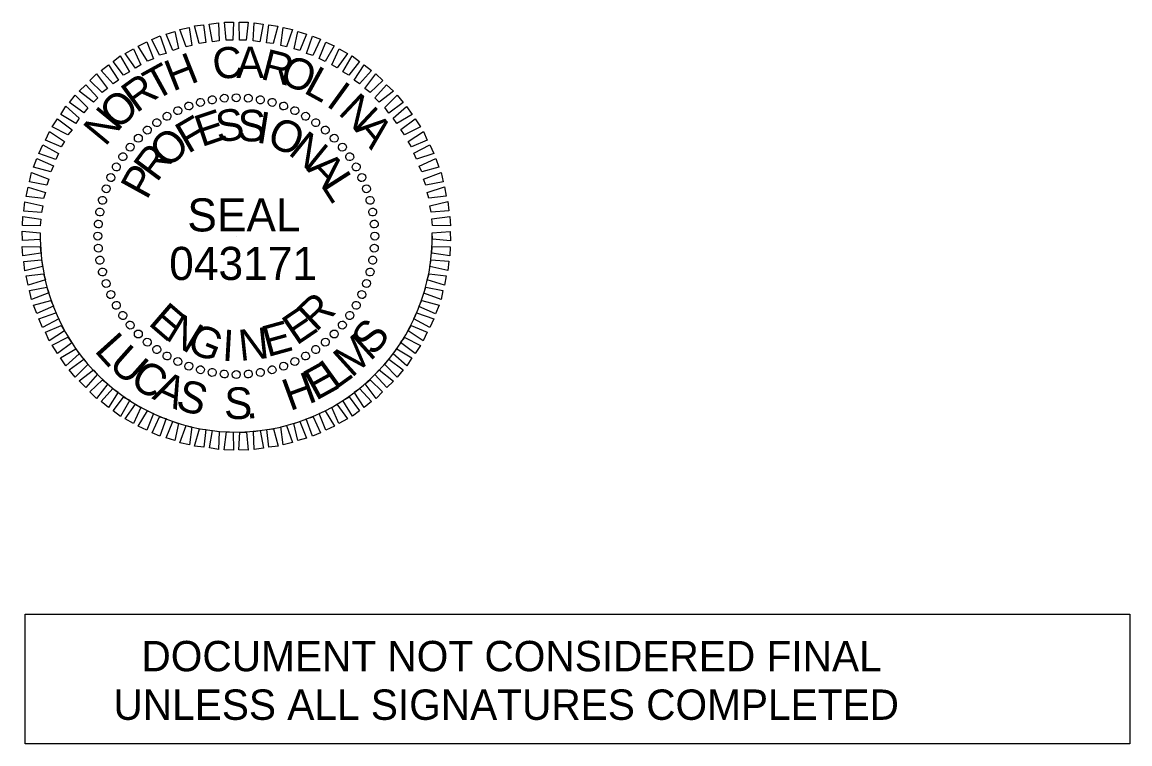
# Model space of a CAD drawing. Extents: x 573078 to 573156.2, y -55225.7 to -55195.8.
# Drawn here: x 573113.18 to 573117.192, y -55203.396 to -55200.78 of the extents above; entities that cross this region are included whole.
import ezdxf

# ---------------------------------------------------------------- set-up
doc = ezdxf.new("R2010")
doc.units = 0
doc.layers.add('Prop Dimension', color=7, linetype='Continuous')
doc.layers.add('Sheet Sticker Exception Certification CELL', color=7, linetype='Continuous')

msp = doc.modelspace()

# ---------------------------------------------------------------- linework, layer by layer
at = {"layer": 'Prop Dimension'}
for p, q in [((573113.7833, -55201.0835), (573113.7833, -55201.0835)), ((573113.8251, -55201.0708), (573113.8251, -55201.0708)), ((573113.869, -55201.062), (573113.869, -55201.062)), ((573113.9118, -55201.0553), (573113.9118, -55201.0553)), ((573113.9558, -55201.0535), (573113.9558, -55201.0535)), ((573113.9999, -55201.0557), (573113.9999, -55201.0557)), ((573114.043, -55201.062), (573114.043, -55201.062)), ((573114.0851, -55201.0703), (573114.0851, -55201.0703)), ((573114.1274, -55201.0835), (573114.1274, -55201.0835)), ((573113.705, -55201.1209), (573113.705, -55201.1209)), ((573113.7436, -55201.1002), (573113.7436, -55201.1002)), ((573114.1677, -55201.1008), (573114.1677, -55201.1008)), ((573114.207, -55201.1201), (573114.207, -55201.1201)), ((573113.6674, -55201.1446), (573113.6674, -55201.1446)), ((573114.2435, -55201.1445), (573114.2435, -55201.1445)), ((573113.6003, -55201.2007), (573113.6003, -55201.2007)), ((573113.6328, -55201.1702), (573113.6328, -55201.1702)), ((573114.2789, -55201.1709), (573114.2789, -55201.1709)), ((573114.3104, -55201.2003), (573114.3104, -55201.2003)), ((573113.5709, -55201.2323), (573113.5709, -55201.2323)), ((573114.341, -55201.2328), (573114.341, -55201.2328)), ((573113.5445, -55201.2677), (573113.5445, -55201.2677)), ((573114.3666, -55201.2674), (573114.3666, -55201.2674)), ((573113.5201, -55201.3041), (573113.5201, -55201.3041)), ((573114.3903, -55201.305), (573114.3903, -55201.305)), ((573113.5008, -55201.3435), (573113.5008, -55201.3435)), ((573114.411, -55201.3436), (573114.411, -55201.3436)), ((573113.4835, -55201.3838), (573113.4835, -55201.3838)), ((573114.4276, -55201.3833), (573114.4276, -55201.3833)), ((573113.4702, -55201.426), (573113.4702, -55201.426)), ((573114.4404, -55201.4251), (573114.4404, -55201.4251)), ((573113.462, -55201.4682), (573113.462, -55201.4682)), ((573114.4491, -55201.469), (573114.4491, -55201.469)), ((573113.4557, -55201.5113), (573113.4557, -55201.5113)), ((573114.4559, -55201.5118), (573114.4559, -55201.5118)), ((573113.4535, -55201.5554), (573113.4535, -55201.5554)), ((573113.9556, -55201.5556), (573113.9556, -55201.5556)), ((573114.4577, -55201.5558), (573114.4577, -55201.5558)), ((573113.4553, -55201.5993), (573113.4553, -55201.5993)), ((573114.4554, -55201.5999), (573114.4554, -55201.5999)), ((573113.462, -55201.6422), (573113.462, -55201.6422)), ((573114.4492, -55201.643), (573114.4492, -55201.643)), ((573113.4708, -55201.6861), (573113.4708, -55201.6861)), ((573114.4409, -55201.6851), (573114.4409, -55201.6851)), ((573114.4277, -55201.7274), (573114.4277, -55201.7274)), ((573113.4835, -55201.7279), (573113.4835, -55201.7279)), ((573113.5002, -55201.7676), (573113.5002, -55201.7676)), ((573114.4104, -55201.7677), (573114.4104, -55201.7677)), ((573113.5209, -55201.8062), (573113.5209, -55201.8062)), ((573114.391, -55201.807), (573114.391, -55201.807)), ((573113.5446, -55201.8438), (573113.5446, -55201.8438)), ((573114.3667, -55201.8435), (573114.3667, -55201.8435)), ((573113.5702, -55201.8784), (573113.5702, -55201.8784)), ((573114.3403, -55201.8789), (573114.3403, -55201.8789)), ((573113.6007, -55201.9108), (573113.6007, -55201.9108)), ((573114.3108, -55201.9104), (573114.3108, -55201.9104)), ((573113.6322, -55201.9403), (573113.6322, -55201.9403)), ((573113.6677, -55201.9667), (573113.6677, -55201.9667)), ((573114.2438, -55201.9666), (573114.2438, -55201.9666)), ((573114.2784, -55201.941), (573114.2784, -55201.941)), ((573113.7041, -55201.991), (573113.7041, -55201.991)), ((573114.2062, -55201.9903), (573114.2062, -55201.9903)), ((573113.7435, -55202.0104), (573113.7435, -55202.0104)), ((573113.7838, -55202.0277), (573113.7838, -55202.0277)), ((573113.826, -55202.0409), (573113.826, -55202.0409)), ((573114.0861, -55202.0404), (573114.0861, -55202.0404)), ((573114.1278, -55202.0277), (573114.1278, -55202.0277)), ((573114.1676, -55202.011), (573114.1676, -55202.011)), ((573113.8682, -55202.0492), (573113.8682, -55202.0492)), ((573113.9113, -55202.0554), (573113.9113, -55202.0554)), ((573113.9553, -55202.0577), (573113.9553, -55202.0577)), ((573113.9993, -55202.0559), (573113.9993, -55202.0559)), ((573114.0422, -55202.0492), (573114.0422, -55202.0492))]:
    msp.add_line(p, q, dxfattribs=at)
for points in [[(573113.7736, -55200.8697), (573113.7515, -55200.807), (573113.7854, -55200.7994), (573113.7945, -55200.8643)], [(573113.8214, -55200.8578), (573113.8043, -55200.7941), (573113.8372, -55200.7905), (573113.8453, -55200.8544)], [(573113.8693, -55200.851), (573113.8572, -55200.7872), (573113.8911, -55200.7826), (573113.8932, -55200.8476)], [(573113.9192, -55200.8451), (573113.913, -55200.7802), (573113.9461, -55200.7806), (573113.9432, -55200.8457)], [(573113.9672, -55200.8453), (573113.9661, -55200.7803), (573113.9991, -55200.7807), (573113.9912, -55200.8459)], [(573114.0172, -55200.8474), (573114.0201, -55200.7823), (573114.0532, -55200.7878), (573114.0413, -55200.851)], [(573114.0654, -55200.8546), (573114.0732, -55200.7904), (573114.1063, -55200.7948), (573114.0894, -55200.8571)], [(573114.1166, -55200.8647), (573114.1254, -55200.7995), (573114.1595, -55200.8069), (573114.1376, -55200.8693)], [(573113.6771, -55200.9003), (573113.6501, -55200.8428), (573113.6799, -55200.8303), (573113.702, -55200.8939)], [(573113.7258, -55200.8835), (573113.7018, -55200.8239), (573113.7326, -55200.8144), (573113.7467, -55200.8761)], [(573114.1648, -55200.8768), (573114.1787, -55200.8146), (573114.2099, -55200.824), (573114.1859, -55200.8835)], [(573114.2101, -55200.894), (573114.232, -55200.8307), (573114.2602, -55200.8422), (573114.2332, -55200.9006)], [(573113.5909, -55200.9469), (573113.553, -55200.8935), (573113.5837, -55200.877), (573113.6097, -55200.9345)], [(573113.6335, -55200.9221), (573113.6005, -55200.8667), (573113.6313, -55200.8521), (573113.6553, -55200.9127)], [(573114.2554, -55200.9123), (573114.2794, -55200.8528), (573114.3106, -55200.8663), (573114.2776, -55200.9229)], [(573114.3018, -55200.9345), (573114.3278, -55200.877), (573114.3581, -55200.8935), (573114.321, -55200.9461)], [(573113.5473, -55200.9726), (573113.5095, -55200.9223), (573113.5351, -55200.9028), (573113.5691, -55200.9602)], [(573114.3413, -55200.9608), (573114.3752, -55200.9022), (573114.4016, -55200.9227), (573114.3635, -55200.9724)], [(573113.5099, -55201.0033), (573113.466, -55200.956), (573113.4927, -55200.9346), (573113.5286, -55200.99)], [(573114.3828, -55200.99), (573114.4188, -55200.9344), (573114.4452, -55200.956), (573114.402, -55201.0037)], [(573113.4704, -55201.035), (573113.4257, -55200.9918), (573113.4492, -55200.9673), (573113.4892, -55201.0206)], [(573114.4213, -55201.0204), (573114.4614, -55200.9677), (573114.4858, -55200.9912), (573114.4406, -55201.035)], [(573113.4037, -55201.1092), (573113.351, -55201.0711), (573113.3726, -55201.0447), (573113.4174, -55201.0909)], [(573113.438, -55201.0705), (573113.3863, -55201.0304), (573113.4109, -55201.007), (573113.4538, -55201.0543)], [(573114.4579, -55201.0547), (573114.5001, -55201.007), (573114.5245, -55201.0306), (573114.4732, -55201.0705)], [(573114.4935, -55201.0901), (573114.5387, -55201.0443), (573114.5602, -55201.071), (573114.5079, -55201.1099)], [(573113.3744, -55201.1477), (573113.3198, -55201.1146), (573113.3383, -55201.0853), (573113.387, -55201.1284)], [(573114.5242, -55201.1286), (573114.5725, -55201.0858), (573114.592, -55201.1144), (573114.5365, -55201.1474)], [(573113.3451, -55201.1882), (573113.2886, -55201.1592), (573113.3081, -55201.1308), (573113.3608, -55201.1699)], [(573114.5509, -55201.1691), (573114.6033, -55201.1302), (573114.6228, -55201.1599), (573114.5653, -55201.1889)], [(573113.3218, -55201.2316), (573113.2644, -55201.2076), (573113.2789, -55201.1763), (573113.3335, -55201.2124)], [(573114.5777, -55201.2127), (573114.6331, -55201.1767), (573114.6466, -55201.2075), (573114.59, -55201.2315)], [(573113.3026, -55201.2779), (573113.2402, -55201.256), (573113.2547, -55201.2248), (573113.3123, -55201.2558)], [(573114.5984, -55201.2553), (573114.6569, -55201.2243), (573114.6705, -55201.2561), (573114.6088, -55201.2771)], [(573113.2834, -55201.3223), (573113.2211, -55201.3054), (573113.2336, -55201.2741), (573113.294, -55201.3011)], [(573114.6173, -55201.302), (573114.6778, -55201.2749), (573114.6893, -55201.3057), (573114.6276, -55201.3228)], [(573113.2692, -55201.3705), (573113.207, -55201.3586), (573113.2135, -55201.3255), (573113.2769, -55201.3494)], [(573114.6341, -55201.3497), (573114.6977, -55201.3256), (573114.7043, -55201.3585), (573114.6415, -55201.3706)], [(573113.2571, -55201.4188), (573113.195, -55201.4118), (573113.2014, -55201.3777), (573113.2647, -55201.3976)], [(573114.6469, -55201.3975), (573114.7096, -55201.3774), (573114.7162, -55201.4113), (573114.6533, -55201.4184)], [(573113.25, -55201.4699), (573113.1859, -55201.465), (573113.1893, -55201.4309), (573113.2546, -55201.4458)], [(573114.6568, -55201.4453), (573114.7215, -55201.4302), (573114.7251, -55201.4641), (573114.6612, -55201.4693)], [(573113.2458, -55201.518), (573113.1808, -55201.5171), (573113.1822, -55201.4841), (573113.2474, -55201.4939)], [(573114.6636, -55201.4932), (573114.7285, -55201.4841), (573114.731, -55201.518), (573114.666, -55201.5172)], [(573113.2457, -55201.568), (573113.1808, -55201.5721), (573113.1802, -55201.5381), (573113.2453, -55201.544)], [(573114.6655, -55201.5432), (573114.7304, -55201.5391), (573114.731, -55201.5731), (573114.6659, -55201.5672)], [(573113.2476, -55201.618), (573113.1827, -55201.6271), (573113.1801, -55201.5931), (573113.2451, -55201.594)], [(573114.6653, -55201.5932), (573114.7304, -55201.5941), (573114.7289, -55201.6271), (573114.6638, -55201.6172)], [(573113.2544, -55201.6658), (573113.1897, -55201.681), (573113.1861, -55201.647), (573113.25, -55201.6419)], [(573114.6612, -55201.6413), (573114.7253, -55201.6462), (573114.7219, -55201.6802), (573114.6566, -55201.6654)], [(573113.2642, -55201.7137), (573113.2016, -55201.7338), (573113.195, -55201.6999), (573113.2579, -55201.6928)], [(573114.6541, -55201.6924), (573114.7162, -55201.6993), (573114.7098, -55201.7335), (573114.6464, -55201.7136)], [(573113.2771, -55201.7615), (573113.2135, -55201.7856), (573113.2069, -55201.7527), (573113.2697, -55201.7406)], [(573114.6419, -55201.7406), (573114.7041, -55201.7526), (573114.6977, -55201.7857), (573114.6343, -55201.7618)], [(573113.2939, -55201.8092), (573113.2334, -55201.8362), (573113.2218, -55201.8054), (573113.2835, -55201.7884)], [(573114.6278, -55201.7889), (573114.6901, -55201.8058), (573114.6776, -55201.837), (573114.6171, -55201.8101)], [(573113.3127, -55201.8559), (573113.2543, -55201.8869), (573113.2407, -55201.8551), (573113.3023, -55201.834)], [(573114.6085, -55201.8332), (573114.6709, -55201.8551), (573114.6565, -55201.8864), (573114.5989, -55201.8554)], [(573113.3335, -55201.8985), (573113.2781, -55201.9345), (573113.2646, -55201.9037), (573113.3211, -55201.8797)], [(573114.5893, -55201.8796), (573114.6468, -55201.9036), (573114.6323, -55201.9348), (573114.5777, -55201.8988)], [(573113.3602, -55201.942), (573113.3079, -55201.981), (573113.2884, -55201.9513), (573113.3459, -55201.9223)], [(573114.5661, -55201.923), (573114.6226, -55201.952), (573114.6031, -55201.9804), (573114.5504, -55201.9413)], [(573113.3869, -55201.9826), (573113.3387, -55202.0254), (573113.3192, -55201.9968), (573113.3746, -55201.9638)], [(573114.5368, -55201.9635), (573114.5914, -55201.9966), (573114.5729, -55202.0259), (573114.5241, -55201.9827)], [(573113.4176, -55202.021), (573113.3724, -55202.0668), (573113.3509, -55202.0402), (573113.4033, -55202.0013)], [(573114.5075, -55202.002), (573114.5601, -55202.0401), (573114.5386, -55202.0665), (573114.4938, -55202.0203)], [(573113.4532, -55202.0564), (573113.4111, -55202.1042), (573113.3867, -55202.0806), (573113.438, -55202.0407)], [(573114.4731, -55202.0406), (573114.5248, -55202.0807), (573114.5002, -55202.1042), (573114.4574, -55202.0569)], [(573113.4899, -55202.0908), (573113.4498, -55202.1435), (573113.4254, -55202.1199), (573113.4706, -55202.0761)], [(573114.4407, -55202.0762), (573114.4855, -55202.1194), (573114.4619, -55202.1438), (573114.422, -55202.0905)], [(573113.5284, -55202.1211), (573113.4924, -55202.1768), (573113.466, -55202.1552), (573113.5091, -55202.1075)], [(573114.4013, -55202.1079), (573114.4451, -55202.1551), (573114.4185, -55202.1766), (573114.3825, -55202.1212)], [(573113.5699, -55202.1504), (573113.5359, -55202.209), (573113.5096, -55202.1885), (573113.5477, -55202.1388)], [(573113.6094, -55202.1767), (573113.5834, -55202.2342), (573113.5531, -55202.2177), (573113.5902, -55202.1651)], [(573114.3203, -55202.1643), (573114.3582, -55202.2177), (573114.3275, -55202.2342), (573114.3015, -55202.1766)], [(573114.3638, -55202.1386), (573114.4017, -55202.1889), (573114.376, -55202.2083), (573114.342, -55202.1509)], [(573113.6558, -55202.1989), (573113.6318, -55202.2583), (573113.6006, -55202.2449), (573113.6336, -55202.1883)], [(573114.2777, -55202.1891), (573114.3107, -55202.2445), (573114.2799, -55202.259), (573114.2558, -55202.1984)], [(573113.7011, -55202.2171), (573113.6792, -55202.2805), (573113.651, -55202.269), (573113.678, -55202.2105)], [(573113.7464, -55202.2343), (573113.7325, -55202.2966), (573113.7013, -55202.2871), (573113.7253, -55202.2277)], [(573113.7946, -55202.2465), (573113.7858, -55202.3117), (573113.7516, -55202.3043), (573113.7735, -55202.2419)], [(573114.1376, -55202.2415), (573114.1597, -55202.3041), (573114.1258, -55202.3117), (573114.1167, -55202.2469)], [(573114.1853, -55202.2277), (573114.2094, -55202.2873), (573114.1786, -55202.2968), (573114.1645, -55202.235)], [(573114.2341, -55202.2108), (573114.2611, -55202.2684), (573114.2313, -55202.2809), (573114.2092, -55202.2173)], [(573113.8458, -55202.2566), (573113.8379, -55202.3208), (573113.8048, -55202.3163), (573113.8218, -55202.254)], [(573113.8939, -55202.2638), (573113.8911, -55202.3288), (573113.858, -55202.3234), (573113.8699, -55202.2602)], [(573113.944, -55202.2659), (573113.9451, -55202.3309), (573113.9121, -55202.3305), (573113.92, -55202.2653)], [(573113.992, -55202.2661), (573113.9981, -55202.331), (573113.9651, -55202.3305), (573113.968, -55202.2655)], [(573114.0419, -55202.2602), (573114.054, -55202.324), (573114.0201, -55202.3286), (573114.0179, -55202.2636)], [(573114.0898, -55202.2534), (573114.1069, -55202.3171), (573114.074, -55202.3206), (573114.0658, -55202.2568)]]:
    msp.add_lwpolyline(points, close=True, dxfattribs=at)
msp.add_arc((573113.9556, -55201.5556), 0.71, 181, 1, dxfattribs=at)
for centre, major_axis in [((573113.9119, -55201.0559), (-0.0013, 0.0143)), ((573113.9556, -55201.054), (0, 0.0144)), ((573113.9993, -55201.0559), (0.0013, 0.0143)), ((573113.7436, -55201.101), (-0.0061, 0.0131)), ((573113.784, -55201.0842), (-0.0049, 0.0135)), ((573113.8258, -55201.0711), (-0.0037, 0.0139)), ((573113.8685, -55201.0616), (-0.0025, 0.0142)), ((573114.0427, -55201.0616), (0.0025, 0.0142)), ((573114.0854, -55201.0711), (0.0037, 0.0139)), ((573114.1271, -55201.0842), (0.0049, 0.0135)), ((573114.1676, -55201.101), (0.0061, 0.0131)), ((573113.7048, -55201.1212), (-0.0072, 0.0125)), ((573114.2064, -55201.1212), (0.0072, 0.0125)), ((573113.6332, -55201.1713), (-0.0093, 0.011)), ((573113.6679, -55201.1447), (-0.0083, 0.0118)), ((573114.2433, -55201.1447), (0.0083, 0.0118)), ((573114.278, -55201.1713), (0.0093, 0.011)), ((573113.6009, -55201.2009), (-0.0102, 0.0102)), ((573114.3103, -55201.2009), (0.0102, 0.0102)), ((573113.5713, -55201.2332), (-0.011, 0.0093)), ((573114.3398, -55201.2332), (0.011, 0.0093)), ((573113.5447, -55201.2679), (-0.0118, 0.0083)), ((573114.3665, -55201.2679), (0.0118, 0.0083)), ((573113.5212, -55201.3048), (-0.0125, 0.0072)), ((573114.39, -55201.3048), (0.0125, 0.0072)), ((573113.501, -55201.3436), (-0.0131, 0.0061)), ((573114.4102, -55201.3436), (0.0131, 0.0061)), ((573113.4842, -55201.384), (-0.0135, 0.0049)), ((573114.4269, -55201.384), (0.0135, 0.0049)), ((573113.4711, -55201.4258), (-0.0139, 0.0037)), ((573114.4401, -55201.4258), (0.0139, 0.0037)), ((573113.4616, -55201.4685), (-0.0142, 0.0025)), ((573114.4496, -55201.4685), (0.0142, 0.0025)), ((573113.4559, -55201.5119), (-0.0143, 0.0013)), ((573114.4553, -55201.5119), (0.0143, 0.0013)), ((573113.454, -55201.5556), (-0.0144, 0)), ((573114.4572, -55201.5556), (0.0144, 0)), ((573113.4559, -55201.5993), (-0.0143, -0.0013)), ((573114.4553, -55201.5993), (0.0143, -0.0013)), ((573113.4616, -55201.6427), (-0.0142, -0.0025)), ((573114.4496, -55201.6427), (0.0142, -0.0025)), ((573113.4711, -55201.6854), (-0.0139, -0.0037)), ((573114.4401, -55201.6854), (0.0139, -0.0037)), ((573113.4842, -55201.7271), (-0.0135, -0.0049)), ((573114.4269, -55201.7271), (0.0135, -0.0049)), ((573113.501, -55201.7676), (-0.0131, -0.0061)), ((573114.4102, -55201.7676), (0.0131, -0.0061)), ((573113.5212, -55201.8064), (-0.0125, -0.0072)), ((573114.39, -55201.8064), (0.0125, -0.0072)), ((573113.5447, -55201.8433), (-0.0118, -0.0083)), ((573114.3665, -55201.8433), (0.0118, -0.0083)), ((573113.5713, -55201.878), (-0.011, -0.0093)), ((573114.3398, -55201.878), (0.011, -0.0093)), ((573113.6009, -55201.9103), (-0.0102, -0.0102)), ((573113.6332, -55201.9398), (-0.0093, -0.011)), ((573114.278, -55201.9398), (0.0093, -0.011)), ((573114.3103, -55201.9103), (0.0102, -0.0102)), ((573113.6679, -55201.9665), (-0.0083, -0.0118)), ((573114.2433, -55201.9665), (0.0083, -0.0118)), ((573113.7048, -55201.99), (-0.0072, -0.0125)), ((573113.7436, -55202.0102), (-0.0061, -0.0131)), ((573114.1676, -55202.0102), (0.0061, -0.0131)), ((573114.2064, -55201.99), (0.0072, -0.0125)), ((573113.784, -55202.0269), (-0.0049, -0.0135)), ((573113.8258, -55202.0401), (-0.0037, -0.0139)), ((573113.8685, -55202.0496), (-0.0025, -0.0142)), ((573113.9119, -55202.0553), (-0.0013, -0.0143)), ((573113.9556, -55202.0572), (0, -0.0144)), ((573113.9993, -55202.0553), (0.0013, -0.0143)), ((573114.0427, -55202.0496), (0.0025, -0.0142)), ((573114.0854, -55202.0401), (0.0037, -0.0139)), ((573114.1271, -55202.0269), (0.0049, -0.0135))]:
    msp.add_ellipse(centre, major_axis=major_axis, ratio=0.999708, dxfattribs=at)
at = {"layer": 'Sheet Sticker Exception Certification CELL'}
for p, q in [((573113.1908, -55203.3956), (573113.1908, -55202.9256)), ((573113.1908, -55202.9256), (573117.1916, -55202.9256)), ((573117.1916, -55202.9256), (573117.1916, -55203.3956)), ((573117.1916, -55203.3956), (573113.1908, -55203.3956))]:
    msp.add_line(p, q, dxfattribs=at)

# ---------------------------------------------------------------- texts
at = {"layer": 'Prop Dimension'}
for s, height, rotation, p in [('C', 0.1128, 7.2199, (573113.8767, -55200.9899)), ('A', 0.1128, 0.0203, (573113.9556, -55200.9825)), ('R', 0.1128, 345.6211, (573114.0396, -55200.985)), ('T', 0.1128, 28.8198, (573113.661, -55201.0667)), ('H', 0.1128, 21.6195, (573113.7254, -55201.0325)), ('O', 0.1128, 338.4212, (573114.1069, -55200.9989)), ('L', 0.1128, 331.2209, (573114.1955, -55201.0343)), ('R', 0.1128, 36.0205, (573113.5938, -55201.1118)), ('I', 0.1128, 324.0201, (573114.2773, -55201.0809)), ('O', 0.1128, 43.2217, (573113.5259, -55201.175)), ('N', 0.1128, 316.8189, (573114.3209, -55201.1111)), ('N', 0.1128, 50.4235, (573113.4809, -55201.2338)), ('F', 0.1144, 30.3, (573113.7805, -55201.2587)), ('E', 0.1144, 18.6709, (573113.8296, -55201.2335)), ('S', 0.1144, 7.1833, (573113.888, -55201.2163)), ('S', 0.1144, 359.4778, (573113.9599, -55201.2119)), ('I', 0.1144, 351.0931, (573114.0248, -55201.2159)), ('O', 0.1144, 336.3611, (573114.0603, -55201.2223)), ('A', 0.1128, 309.6172, (573114.3809, -55201.1691)), ('O', 0.1144, 44.5875, (573113.7095, -55201.3146)), ('N', 0.1144, 320.95, (573114.1398, -55201.2565)), ('R', 0.1144, 53.4166, (573113.6678, -55201.3639)), ('A', 0.1144, 313.2445, (573114.2077, -55201.3149)), ('P', 0.1144, 61.1222, (573113.6315, -55201.4274)), ('L', 0.1144, 302.6752, (573114.2593, -55201.3707)), ('SEAL', 0.11996, 360, (573113.7783, -55201.5387)), ('043171', 0.12, 360, (573113.7126, -55201.7145)), ('E', 0.1128, 319.2769, (573113.6331, -55201.8743)), ('R', 0.1128, 43.4814, (573114.2437, -55201.9056)), ('N', 0.1128, 328.634, (573113.694, -55201.9272)), ('E', 0.1128, 34.1241, (573114.1736, -55201.9538)), ('G', 0.1128, 337.9902, (573113.7708, -55201.9709)), ('N', 0.1128, 6.0564, (573113.9695, -55202.0084)), ('E', 0.1128, 15.4118, (573114.0683, -55201.9947)), ('S', 0.115, 51.8121, (573114.4537, -55201.9943)), ('L', 0.115, 312.0206, (573113.4385, -55201.9718)), ('I', 0.1128, 356.7012, (573113.9024, -55202.0066)), ('M', 0.115, 42.1638, (573114.3731, -55202.0716)), ('U', 0.115, 318.4043, (573113.488, -55202.0267)), ('E', 0.115, 28.8778, (573114.2433, -55202.1537)), ('L', 0.115, 35.78, (573114.3131, -55202.1148)), ('C', 0.115, 327.0636, (573113.5643, -55202.0917)), ('H', 0.115, 20.1897, (573114.1497, -55202.1903)), ('A', 0.115, 335.5021, (573113.6472, -55202.1434)), ('S', 0.115, 343.4797, (573113.7317, -55202.1805)), ('S', 0.115, 359.3389, (573113.911, -55202.2179)), ('.', 0.115, 6.3756, (573113.9925, -55202.2183))]:
    msp.add_text(s, height=height, rotation=rotation, dxfattribs=at).set_placement(p)
at = {"layer": 'Sheet Sticker Exception Certification CELL'}
for s, p in [('DOCUMENT NOT CONSIDERED FINAL', (573113.6122, -55203.1325)), ('UNLESS ALL SIGNATURES COMPLETED', (573113.5108, -55203.3085))]:
    msp.add_text(s, height=0.11, dxfattribs=at).set_placement(p)

doc.saveas('drawing.dxf')
